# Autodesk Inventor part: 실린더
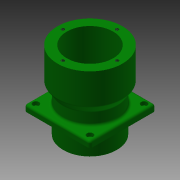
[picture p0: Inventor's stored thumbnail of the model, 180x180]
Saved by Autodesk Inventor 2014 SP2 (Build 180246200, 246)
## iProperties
Created: 2016-11
Part Number: 실린더
Material: 알루미늄 6061
Document SubType Name: Modeling
Designer: mduedu
Density: 2.71 g/cm^3
Mass: 551.099 g
Surface Area: 551.337 cm^2
Volume: 203.358 cm^3
Appearance: 진녹색
Author: mduedu
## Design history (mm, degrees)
sketch "스케치1"
  geometry: L1 (0, 0)-(0, 101); L2 (30, 0)-(30, 101); L3 (30, 101)-(42, 101); L4 (42, 101)-(42, 61); L5 (42, 61)-(35, 51); L6 (35, 51)-(35, 0); L7 (35, 0)-(30, 0)
  constraints: 14 end point, 4 parallel, 2 horizontal alignment, 1 perpendicular, 1 vertical
  dimensions: "d0" = 101 distance of L1.start L1.end; "d1" = 60 diameter of L2.end L1; "d2" = 84 diameter of L3.end L1; "d3" = 70 diameter of L6.end L1; "d4" = 40 distance of L3.end L4.end; "d5" = 50 vertical distance of L5.end L3.end
revolve "회전1" sketch "스케치1" stored, may be unused: angle "d6" = 90 deg
node "작업 평면1"
sketch "스케치2"
  geometry: L1 (-42.5, -42.5)-(42.5, -42.5); L2 (42.5, -42.5)-(42.5, 42.5); L3 (42.5, 42.5)-(-42.5, 42.5); L4 (-42.5, 42.5)-(-42.5, -42.5); L5 (-42.5, -42.5)-(42.5, 42.5); L6 (42.5, -42.5)-(-42.5, 42.5); C1 r 35 at (0, 0) reference; C2 r 35 at (0, 0); 1 further point
  constraints: 12 end point, 2 midpoint, 2 parallel, 2 perpendicular, 1 centre point, 1 coincident, 1 concentric, 1 horizontal
  dimensions: "d8" = 85 distance of L2.end L3.end
extrude "돌출1" join sketch "스케치2" distance "d10" = 8; taper "d11" = 0 deg
fillet "모깎기1" dims "d12" = 3
fillet "모깎기2" dims "d13" = 3
chamfer "모따기1" distance "d14" = 1; stored, may be unused: second distance "d15" = 2, angle "d16" = 45 deg
chamfer "모따기2" distance "d17" = 5; stored, may be unused: second distance "d18" = 2, angle "d19" = 15 deg
sketch "스케치3"
  geometry: L1 (-35, -35)-(35, -35); L2 (35, -35)-(35, 35); L3 (35, 35)-(-35, 35); L4 (-35, 35)-(-35, -35); L5 (-35, -35)-(35, 35); L6 (35, -35)-(-35, 35); 5 further points
  constraints: 12 end point, 4 coincident, 2 midpoint, 2 parallel, 1 horizontal, 1 perpendicular
  dimensions: "d20" = 70 distance of L3.end L2.end; "d21" = 70 distance of L2.end L1.end
sketch "스케치4"
  geometry: 4 further points
  constraints: 4 other
hole "구멍1" sketch "스케치4" at (-35, 35), (35, 35), (35, -35), (-35, -35) diameter "d22" = 4.5; stored, may be unused: countersink angle "d26" = 90 deg, drill point angle "d28" = 0 deg; dims "d23" = 6, "d24" = 8, "d25" = 4.6, "d27" = 8
sketch "스케치5"
  geometry: 4 further points
  constraints: 4 other
hole "구멍2" sketch "스케치5" at (0, -35), (35, 0), (-35, 0), (0, 35) diameter "d29" = 4.134; stored, may be unused: countersink angle "d33" = 90 deg, drill point angle "d35" = 120 deg; dims "d30" = 7.5, "d31" = 4, "d32" = 2, "d34" = 10
node "솔리드1"
other parameters: "d7" = -27
